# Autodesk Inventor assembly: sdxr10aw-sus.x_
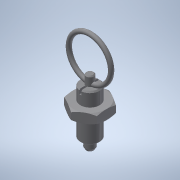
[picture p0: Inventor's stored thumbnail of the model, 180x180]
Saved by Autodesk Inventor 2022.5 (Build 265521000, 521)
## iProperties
Part Number: sdxr10aw-sus.x_
Material: 一般
Document SubType Name: Assembly
Designer: ImaoCorp
Sending System: SOLIDWORKS 2017-2017317
MC: AMD64
MC_MODEL: Intel64 Family 6 Model 60 Stepping 3, GenuineIntel
OS: Windows_NT
FRU: Parasolid Version 29.0, build 201,  4-17-2017
FORMAT: text
GUISE: transmit
KEY: sdxr10aw-sus
FILE: sdxr10aw-sus.x_t
DATE: Wed Sep 18 16:15:52 2019
Author: ImaoCorp
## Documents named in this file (3)
- X:\14_SW2022-Inv2022\00_全2023-1023新製品(TCC)まで\s\sdxr10aw-sus\SDXR10AW-SUS.iam
- X:\14_SW2022-Inv2022\00_全2023-1023新製品(TCC)まで\s\sdxr10aw-sus\sdxr10aw-sus_01.ipt
- X:\14_SW2022-Inv2022\00_全2023-1023新製品(TCC)まで\s\sdxr10aw-sus\sdxr10aw-sus_02.ipt
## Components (2 placed, 2 different names)
1. sdxr10aw-sus_01
2. sdxr10aw-sus_02
